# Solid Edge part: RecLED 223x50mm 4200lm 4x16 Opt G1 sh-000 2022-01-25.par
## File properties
Author: jaroslaw.przewlocki
Template: iso metric part.par
Last saved by: jaroslaw.przewlocki
Revision: 1
Application: Solid Edge
Gęstość: 0,000 kg/m^3
Dokładność: 0,990
Username: jaroslaw.przewlocki
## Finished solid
Body 1: solid body, 7090 faces, 21059 edges, 14085 vertices.
  Faces by surface: plane 4138, cylinder 2690, spline 208, cone 26, torus 11, sphere 10, spun 7
  Edges by curve: line 14216, circle 5555, curve on surface 1050, spline 166, ellipse 66, intersection 6
Bounding box of the edges (mm; curved faces can reach further): 49.500 x 4.950 x 223.000, from (-24.75, -4.95, -111.5) to (24.75, 0, 111.5).
Cylindrical faces by radius (mm): R0.1 x768, R0.15 x1280, R0.2 x295, R0.2002 x2, R0.2169 x3, R0.25 x12, R0.3 x2, R0.3373 x3, R0.4 x264, R0.4006 x2, R0.4008 x2, R0.525 x2, R0.6 x12, R1 x7, R1.05 x16, R1.0894 x2, R1.1 x14, R1.75 x4
Conical faces (half-angle, radius in mm at the cone's reference point): 0.5 deg R0.5056 x4, 0.5 deg R1.0082 x4, 1 deg R0.5511 x2, 10 deg R0.2132 x2, 10 deg R0.4132 x2, 18.4844 deg R1.0657 x4, 27.363 deg R0.6214 x2, 45 deg R0.575 x2, 45 deg R0.625 x4
Toroidal faces (ring radius, tube radius in mm): R0.1 r0.2 x1, R0.8 r0.2 x4, R0.8522 r0.3 x2, R0.9002 r0.2 x1, R0.9018 r0.2 x1, R1.3 r0.2 x2
Spherical faces by radius (mm): R0.2 x8, R0.6 x2
Planar faces by outward normal: +x 846, +y 136, +z 906, -x 846, -y 341, -z 915, oblique 148
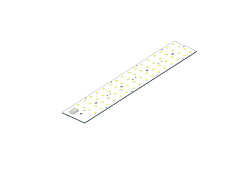
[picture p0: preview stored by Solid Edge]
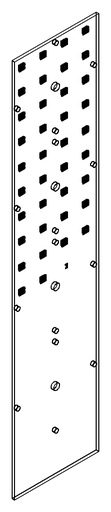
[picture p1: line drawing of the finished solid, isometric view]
